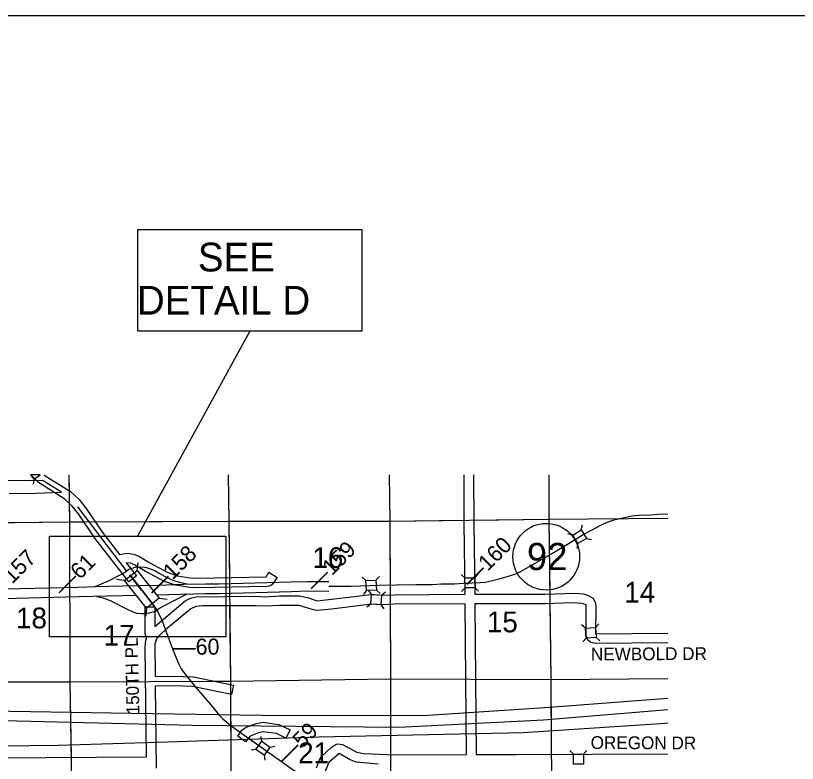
# Model space of a CAD drawing. Extents: x 10133 to 81668, y 5524 to 11018.
# Drawn here: x 22301 to 22912, y 9359 to 9944 of the extents above; entities that cross this region are included whole.
import ezdxf

# ---------------------------------------------------------------- set-up
doc = ezdxf.new("R2010")
doc.units = 0
for name, color, linetype in [('Default', 7, 'Continuous'), ('DisCLMLSUR', 7, 'Continuous'), ('Level 3', 7, 'Continuous'), ('trf_Signal_(Temp)_Layout', 7, 'Continuous')]:
    doc.layers.add(name, color=color, linetype=linetype)

msp = doc.modelspace()

# ---------------------------------------------------------------- linework, layer by layer
at = {"layer": 'Default'}
for p, q in [((22319.8, 9585.14), (22312.4, 9585.14)), ((22315.05, 9581.59), (22314.49, 9577.72)), ((22742.78, 9542.04), (22743.7, 9545.84)), ((22736.1, 9537.96), (22732.3, 9538.89)), ((22740.17, 9531.28), (22739.25, 9527.48)), ((22746.85, 9535.35), (22750.66, 9534.43)), ((22395.68, 9510.25), (22396.4, 9516.46)), ((22651.68, 9504.37), (22648.83, 9507.05)), ((22659.5, 9504.61), (22662.18, 9507.46)), ((22385.89, 9502.48), (22379.68, 9503.19)), ((22574.52, 9502.28), (22571.63, 9504.92)), ((22582.33, 9502.63), (22584.97, 9505.52)), ((22574.86, 9494.47), (22572.22, 9491.58)), ((22578.89, 9491.74), (22576.37, 9494.73)), ((22582.68, 9494.81), (22585.57, 9492.17)), ((22651.92, 9496.55), (22649.24, 9493.7)), ((22659.74, 9496.79), (22662.59, 9494.11)), ((22412.91, 9488.55), (22419.12, 9487.84)), ((22586.69, 9491.06), (22589.68, 9493.57)), ((22578.21, 9483.94), (22575.21, 9481.43)), ((22586.01, 9483.26), (22588.52, 9480.27)), ((22403.13, 9480.78), (22402.41, 9474.57)), ((22746.01, 9465.19), (22743.08, 9467.78)), ((22753.82, 9465.68), (22756.41, 9468.61)), ((22754.31, 9457.87), (22757.24, 9455.28)), ((22746.5, 9457.38), (22743.91, 9454.44)), ((22493.12, 9376.69), (22492.49, 9380.55)), ((22499.48, 9372.12), (22503.34, 9372.76)), ((22488.55, 9370.33), (22484.69, 9369.7)), ((22494.91, 9365.77), (22495.54, 9361.91)), ((22736.59, 9366.73), (22733.82, 9369.49)), ((22744.42, 9366.74), (22747.18, 9369.52))]:
    msp.add_line(p, q, dxfattribs=at)
for points in [[(22285.13, 9363.68), (22403.02, 9364.64), (22401.97, 9450.17), (22402.14, 9453.81), (22403.07, 9457.4), (22402.04, 9460.72), (22402.04, 9481.86), (22409.54, 9481.86), (22409.55, 9466.47), (22433.15, 9486.43), (22437.34, 9488.53), (22441.71, 9489.75), (22488.26, 9490.18), (22496.05, 9489.73), (22507.01, 9490.46), (22522.58, 9490.34), (22528.81, 9488.99), (22536.31, 9486.59), (22578.69, 9491.47), (22588.05, 9490.83), (22596.18, 9491.31), (22652.11, 9491.65), (22651.26, 9547.22), (22651.15, 9585.14)], [(22295.8, 9570.52), (22316.45, 9570.7), (22336.67, 9571.42), (22325.2, 9578.39), (22321.89, 9580.49), (22312.41, 9580.23), (22293.75, 9580.62)], [(22312.4, 9585.14), (22315.05, 9581.59), (22319.8, 9585.14)], [(22436.54, 9496.92), (22425.59, 9498.86), (22417.05, 9501.68), (22401.93, 9509.64), (22394.01, 9514.51), (22390.77, 9515.86), (22387.14, 9516.21), (22395.25, 9506.02), (22389.28, 9501.49), (22362.53, 9535.52), (22349.85, 9554.41), (22344.83, 9560.63), (22339.16, 9565.86), (22318.53, 9578.92), (22312.61, 9585.12), (22312.6, 9585.14)], [(22322.99, 9585.14), (22323.93, 9584.24), (22343.56, 9571.94), (22350.28, 9565.78), (22355.97, 9558.74), (22368.57, 9539.97), (22381.83, 9522.78), (22387.62, 9523.73), (22392.99, 9523.03), (22397.6, 9521.09), (22405.66, 9516.14), (22419.78, 9508.67), (22427.28, 9506.17), (22437.35, 9504.37), (22442.24, 9504.14), (22496.44, 9505.32), (22498.63, 9508.82), (22504.99, 9504.85), (22501.49, 9499.53), (22499.88, 9498.36), (22497.34, 9497.84), (22442.31, 9496.64), (22436.54, 9496.92)], [(22342.31, 9585.14), (22342.52, 9572.59)], [(22342.31, 9585.14), (22342.94, 9548.24)], [(22466.87, 9585.14), (22467.26, 9548.81)], [(22466.87, 9585.14), (22467.26, 9548.81)], [(22592.73, 9585.14), (22593.14, 9548.88)], [(22592.73, 9585.14), (22593.14, 9548.88)], [(22658.65, 9585.14), (22658.75, 9547.29), (22659.6, 9491.68), (22714.41, 9491.76), (22738.32, 9492.48), (22744.46, 9491.9), (22747.56, 9491.02), (22752.07, 9488.55), (22753.97, 9484.61), (22754.29, 9481.35), (22753.96, 9460.79), (22810.38, 9461.24)], [(22717.32, 9585.14), (22717.36, 9550.38)], [(22717.32, 9585.14), (22717.36, 9550.38)], [(22342.69, 9562.84), (22342.94, 9548.24)], [(22593.14, 9548.88), (22717.36, 9550.38)], [(22593.14, 9548.88), (22651.25, 9549.58)], [(22658.75, 9549.67), (22717.36, 9550.38)], [(22717.36, 9550.38), (22810.38, 9551.16)], [(22717.36, 9550.38), (22810.38, 9551.16)], [(22717.36, 9550.38), (22718.16, 9491.83)], [(22717.36, 9550.38), (22719.06, 9425.1)], [(22223.58, 9547.02), (22342.94, 9548.24)], [(22278.14, 9547.58), (22342.94, 9548.24)], [(22342.94, 9548.24), (22467.26, 9548.81)], [(22342.94, 9548.24), (22354.07, 9548.29)], [(22342.94, 9548.24), (22343.21, 9423.31)], [(22342.94, 9548.24), (22343.21, 9423.31)], [(22363.09, 9548.33), (22467.26, 9548.81)], [(22467.26, 9548.81), (22593.14, 9548.88)], [(22467.26, 9548.81), (22593.14, 9548.88)], [(22467.26, 9548.81), (22467.74, 9504.66)], [(22467.26, 9548.81), (22468.62, 9423.7)], [(22593.14, 9548.88), (22593.4, 9491.15)], [(22593.14, 9548.88), (22593.7, 9425.52)], [(22363.01, 9497.37), (22349.6, 9497.01), (22281.73, 9495.32), (22268.04, 9495.08), (22263.9, 9495.12), (22259.95, 9495.49), (22254.33, 9496.37), (22246.67, 9498.25), (22191.09, 9518.05), (22190.09, 9518.42)], [(22434.43, 9499.49), (22428.86, 9500.72), (22423.89, 9502.41), (22419.48, 9504.5), (22413.01, 9507.97), (22409.05, 9510.23), (22404.8, 9511.88), (22402.04, 9512.52), (22398.12, 9512.81), (22394.2, 9512.46), (22390.38, 9511.48), (22389.15, 9511.02), (22387.63, 9509.79)], [(22387.63, 9509.79), (22385.38, 9508.05), (22372.43, 9501.73), (22362.68, 9497.45), (22362.39, 9497.35)], [(22399.47, 9494.57), (22397.56, 9496.97), (22397, 9497.69), (22394.84, 9500.44), (22392.97, 9502.82), (22389.99, 9506.74)], [(22390, 9506.74), (22392.98, 9502.83), (22407.62, 9484.11), (22410.98, 9479.15), (22413.2, 9475.21), (22415.61, 9470.13), (22423.42, 9449.08), (22427.91, 9437.61), (22430.2, 9433.33), (22432.94, 9429.33), (22441.96, 9418.35), (22453, 9405.37), (22460.03, 9396.92), (22462.59, 9394.3), (22468.96, 9389), (22472.94, 9386.26), (22508.58, 9360.95), (22526.77, 9347.85)], [(22408.85, 9482.29), (22407.61, 9484.11), (22403.27, 9489.78), (22402, 9491.38), (22400.28, 9493.55), (22399.47, 9494.57)], [(22467.82, 9497.16), (22467.9, 9489.81)], [(22411.2, 9479.22), (22412.63, 9480.39), (22416.94, 9482.9), (22433.28, 9491.11), (22435.3, 9491.94)], [(22535.74, 9356.05), (22538.2, 9362.29), (22539.7, 9364.7), (22547.36, 9371.95), (22550.41, 9374.02), (22552.22, 9374.58), (22556.13, 9374.3), (22567.33, 9368.16), (22572.71, 9367.14), (22597.3, 9366.04), (22653.03, 9366.37), (22652.13, 9484.15), (22596.23, 9483.81), (22588.1, 9483.33), (22578.96, 9483.97), (22547.71, 9480.07), (22536.16, 9479.08), (22533.55, 9479.4), (22522.28, 9482.84), (22507.24, 9482.97), (22496.03, 9482.23), (22488.18, 9482.68), (22446.64, 9482.48), (22441.6, 9482.09), (22437.55, 9480.35), (22417.74, 9463.75), (22411.96, 9458.35), (22410.88, 9456.73), (22409.56, 9452.71), (22409.7, 9427.27), (22423.68, 9427.51), (22439.81, 9427.03), (22470.88, 9420.57), (22469.51, 9413.19), (22438.84, 9419.58), (22423.75, 9420.01), (22409.76, 9419.76), (22410.63, 9355.71)], [(22467.98, 9482.32), (22468.62, 9423.7)], [(22593.43, 9483.65), (22593.7, 9425.52)], [(22810.38, 9453.72), (22754, 9453.24), (22750.35, 9453.99), (22747.94, 9455.85), (22746.54, 9459.44), (22746.51, 9483.36), (22743.22, 9484.5), (22735.7, 9484.98), (22714.49, 9484.27), (22659.63, 9484.19), (22660.53, 9366.4), (22691.92, 9366.35)], [(22718.26, 9484.33), (22719.06, 9425.1)], [(22223.86, 9423.18), (22343.21, 9423.31)], [(22284.55, 9423.25), (22343.21, 9423.31)], [(22343.21, 9423.31), (22468.62, 9423.7)], [(22343.21, 9423.31), (22402.31, 9423.49)], [(22343.21, 9423.31), (22344.14, 9364.33)], [(22343.21, 9423.31), (22345.2, 9298.26)], [(22454.87, 9423.66), (22468.62, 9423.7)], [(22468.62, 9423.7), (22593.7, 9425.52)], [(22468.62, 9423.7), (22593.7, 9425.52)], [(22468.62, 9423.7), (22468.62, 9420.99)], [(22468.62, 9423.7), (22469.06, 9299.65)], [(22593.7, 9425.52), (22652.79, 9425.33)], [(22593.7, 9425.52), (22593.75, 9366.13)], [(22593.7, 9425.52), (22593.82, 9299.69)], [(22593.7, 9425.52), (22719.06, 9425.1)], [(22660.29, 9425.3), (22719.06, 9425.1)], [(22719.06, 9425.1), (22810.38, 9425.74)], [(22719.06, 9425.1), (22810.38, 9425.74)], [(22719.06, 9425.1), (22719.34, 9366.46)], [(22719.06, 9425.1), (22719.65, 9300.38)], [(22810.38, 9410.15), (22717.96, 9403.04), (22623.16, 9396.95), (22509.76, 9396.68), (22390.89, 9398.43), (22280.47, 9400.16), (22182.2, 9400.62), (22096.83, 9391.49), (22014.43, 9384.88), (21991.02, 9383.7)], [(22468.65, 9413.36), (22469.06, 9299.65)], [(22810.38, 9401.29), (22713.24, 9393.25), (22600.32, 9387.44), (22438.78, 9389.03), (22291.63, 9392.6), (22193.11, 9394.31), (22095.57, 9378.93), (21991.02, 9373.88)], [(22810.38, 9390.93), (22808.53, 9390.54), (22697.35, 9383.22), (22537.78, 9380.03), (22419.41, 9376), (22334.04, 9373.41), (22244.96, 9372.33), (22145.7, 9375.3), (22072.49, 9371.94), (21991.34, 9366.58), (21991.02, 9366.54)], [(22480.31, 9376.37), (22474.26, 9380.8), (22477.81, 9385.58), (22480.96, 9387.69), (22488.21, 9390.46), (22493.92, 9391.6), (22506.5, 9389.92), (22515.26, 9385.67), (22511.78, 9379.03), (22504.47, 9382.68), (22494.3, 9384.11), (22490.41, 9383.29), (22483.89, 9380.74), (22480.31, 9376.37)], [(22583.94, 9358.86), (22566.92, 9360.42), (22561.77, 9362.51), (22553.68, 9367.21), (22545.62, 9360.09), (22542.07, 9352.03)], [(22691.92, 9366.35), (22810.38, 9366.83)]]:
    msp.add_lwpolyline(points, dxfattribs=at)
for points in [[(22736.1, 9537.96), (22742.78, 9542.04), (22746.85, 9535.35), (22740.17, 9531.28)], [(22403.13, 9480.78), (22385.89, 9502.48), (22395.68, 9510.25), (22412.91, 9488.55)], [(22574.52, 9502.28), (22582.33, 9502.63), (22582.68, 9494.81), (22574.86, 9494.47)], [(22651.68, 9504.37), (22659.5, 9504.61), (22659.74, 9496.79), (22651.92, 9496.55)], [(22578.89, 9491.74), (22586.69, 9491.06), (22586.01, 9483.26), (22578.21, 9483.94)], [(22753.82, 9465.68), (22754.31, 9457.87), (22746.5, 9457.38), (22746.01, 9465.19)], [(22494.91, 9365.77), (22488.55, 9370.33), (22493.12, 9376.69), (22499.48, 9372.12)], [(22736.59, 9366.73), (22744.42, 9366.74), (22744.43, 9358.92), (22736.61, 9358.91)]]:
    msp.add_lwpolyline(points, close=True, dxfattribs=at)
msp.add_circle((22715.43, 9521.01), 26.06, dxfattribs=at)
at = {"layer": 'Level 3'}
msp.add_lwpolyline([(20932.52, 9944.02), (24067.53, 9944.02), (24067.53, 7924.02), (20932.52, 7924.02)], close=True, dxfattribs=at)
at = {"layer": 'trf_Signal_(Temp)_Layout'}
msp.add_line((22483.72, 9697.28), (22396.03, 9537.01), dxfattribs=at)
for points in [[(22396.16, 9776.77), (22571.27, 9776.77), (22571.27, 9697.28), (22396.16, 9697.28)], [(22327.17, 9458.25), (22327.17, 9537.01), (22464.9, 9537.01), (22464.9, 9458.25)]]:
    msp.add_lwpolyline(points, close=True, dxfattribs=at)
for points in [[(22395.23, 9490.71), (22349.73, 9489.51), (22281.82, 9487.82), (22268.03, 9487.58), (22263.52, 9487.62), (22259.02, 9488.04), (22252.98, 9488.99), (22244.64, 9491.03), (22188.52, 9511), (22160.08, 9521.51), (22132.84, 9531.16), (22111.4, 9538.58), (22097.52, 9544.03), (22059.04, 9557.56), (22042.16, 9564.24), (22034.66, 9568.69), (22030.51, 9571.55), (22025.98, 9575.38), (22022.81, 9578.75), (22018.05, 9585.14)], [(22387.49, 9509.9), (22349.46, 9560.02)], [(22545.58, 9497.86), (22563.04, 9498.05), (22584.81, 9498.83), (22598.19, 9498.92), (22613.57, 9499.32), (22626.71, 9499.29), (22633.12, 9499.75), (22643.75, 9499.91), (22650.87, 9500.43), (22663.82, 9500.8), (22667.86, 9501.18), (22678.49, 9503.6), (22684.2, 9505.18), (22690.76, 9507.39), (22694.96, 9509.26), (22720.17, 9523.73), (22731.95, 9530.76), (22743.38, 9537.82), (22757.48, 9545.53), (22762.43, 9547.8), (22767.56, 9549.64), (22776.4, 9551.75), (22782.44, 9552.93), (22787.66, 9553.54), (22797.3, 9553.76), (22802.32, 9554.16), (22810.38, 9554.43)], [(22405.01, 9498.51), (22431.95, 9499.43), (22449.38, 9499.87), (22459.8, 9499.87), (22515.82, 9501.3), (22528.76, 9501.73), (22545.61, 9501.61)], [(22406.04, 9498.51), (22363.01, 9497.37)], [(22410.8, 9491.2), (22449.47, 9492.37), (22459.89, 9492.37), (22516.33, 9493.81), (22528.61, 9494.23), (22545.54, 9494.11)], [(22364.18, 9489.89), (22368.01, 9488.99), (22372.13, 9487.68), (22375.17, 9486.44), (22387.5, 9480.16), (22391.92, 9478.09), (22395.49, 9476.99), (22399.19, 9476.49), (22401.68, 9476.5), (22405.23, 9477.04), (22409.35, 9478.12), (22410.47, 9478.62), (22411.2, 9479.22)]]:
    msp.add_lwpolyline(points, dxfattribs=at)

# ---------------------------------------------------------------- texts
at = {"layer": 'Default'}
for s, height, rotation, p in [('‒‒159', 12.5, 45, (22534.75, 9492.6)), ('‒‒160', 12.5, 45, (22656.6, 9496.05)), ('‒‒160', 12.5, 45, (22656.6, 9496.05)), ('‒‒157', 12.5, 45, (22284.82, 9486.07)), ('‒‒158', 12.5, 45, (22410.31, 9489.34)), ('16', 16.25, 0.01823, (22532.66, 9512.18)), ('‒‒61', 12.5, 45, (22337.87, 9489.46)), ('14', 16.25, 0.01977, (22776.47, 9485.12)), ('18', 16.25, 0.01688, (22301.04, 9464.98)), ('15', 16.25, 0.01913, (22669.03, 9461.9)), ('17', 16.25, 0.01742, (22369.49, 9451.48)), ('150TH PL', 10, 91.21266, (22397.43, 9397.81)), ('NEWBOLD DR', 10, 0.30954, (22750.34, 9439.82)), ('‒‒59', 12.5, 45, (22511.62, 9357.49)), ('OREGON DR', 10, 359.77015, (22750.1, 9370.7)), ('21', 16.25, 0.01824, (22521.52, 9359.54))]:
    msp.add_text(s, height=height, rotation=rotation, dxfattribs=at).set_placement(p)
for s, height, p in [('92', 21.25, (22700.35, 9510.52)), ('‒‒60', 12.5, (22422.82, 9444.44)), ('‒‒60', 12.5, (22422.82, 9444.44))]:
    msp.add_text(s, height=height, dxfattribs=at).set_placement(p)
at = {"layer": 'DisCLMLSUR'}
for s, p in [(' SEE', (22434.75, 9744.02)), ('  DETAIL D', (22378.79, 9710.27))]:
    msp.add_text(s, height=22.5, dxfattribs=at).set_placement(p)

doc.saveas('drawing.dxf')
